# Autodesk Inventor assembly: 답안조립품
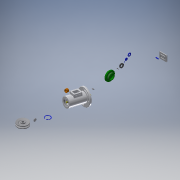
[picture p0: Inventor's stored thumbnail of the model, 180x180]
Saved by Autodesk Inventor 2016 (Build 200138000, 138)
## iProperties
Created: 2017-05
Part Number: 답안조립품
Material: 일반
Document SubType Name: Assembly
Designer: USER
Author: USER
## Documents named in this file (20)
- C:\Users\USER\Desktop\470508V1017\답안조립품.iam
- C:\Users\USER\Desktop\470508V1017\V-벨트풀리.ipt
- C:\Users\USER\Desktop\470508V1017\너트 M10.ipt
- C:\Users\USER\Desktop\470508V1017\멈춤링 15 x 1.ipt
- C:\Users\USER\Desktop\470508V1017\멈춤링 35x1.6.ipt
- C:\Users\USER\Desktop\470508V1017\베어링 15 x 35 x 11.ipt
- C:\Users\USER\Desktop\470508V1017\본체.ipt
- C:\Users\USER\Desktop\470508V1017\볼트 M4 x 10.ipt
- C:\Users\USER\Desktop\470508V1017\부시1.ipt
- C:\Users\USER\Desktop\470508V1017\부시2.ipt
- C:\Users\USER\Desktop\470508V1017\사이드 커버.ipt
- 사이드 커버.ipt
- C:\Users\USER\Desktop\470508V1017\십자볼트 M3 x 10.ipt
- C:\Users\USER\Desktop\470508V1017\오일 실 15 25 7.ipt
- C:\Users\USER\Desktop\470508V1017\와셔 3x6.ipt
- C:\Users\USER\Desktop\470508V1017\와셔 4x16.ipt
- C:\Users\USER\Desktop\470508V1017\와셔 10x21.ipt
- C:\Users\USER\Desktop\470508V1017\축.ipt
- C:\Users\USER\Desktop\470508V1017\키 4 x 4 x 18.ipt
- C:\Users\USER\Desktop\470508V1017\탑 커버.ipt
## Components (2 placed, 2 different names)
1. V-벨트풀리:1
2. ISO 4017 M4 x 10:1
